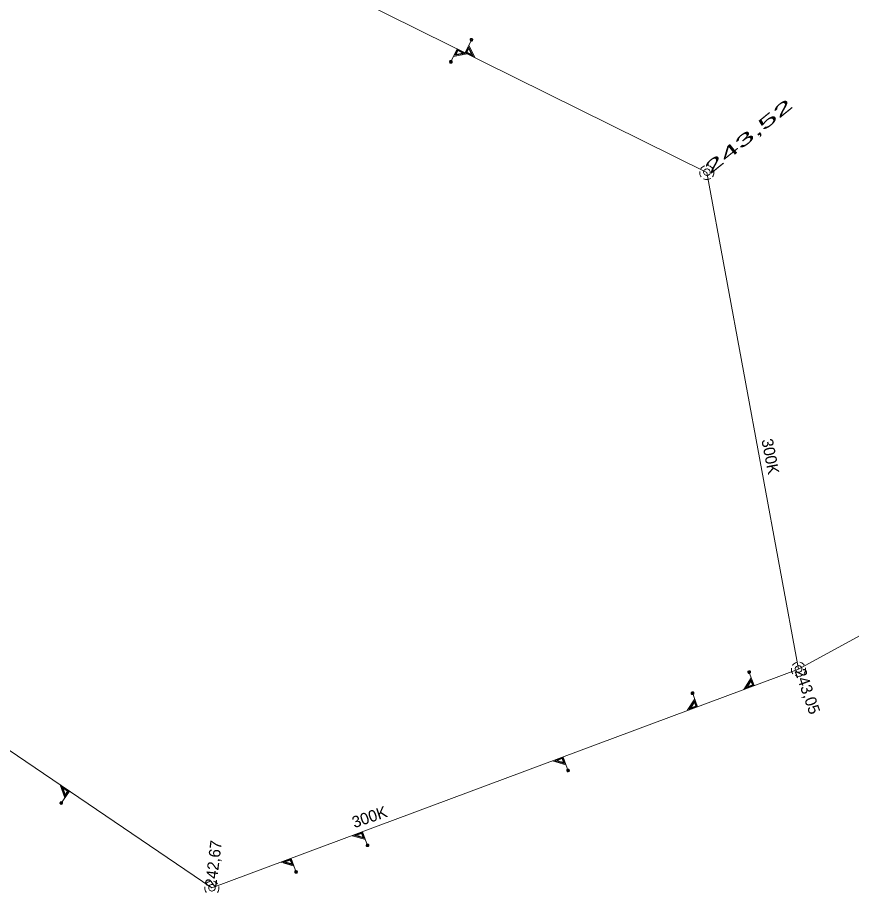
# Model space of a CAD drawing. Extents: x -735085 to -733500, y -1044153 to -1043402.
# Drawn here: x -734770.5 to -734712.5, y -1043657.9 to -1043597 of the extents above; entities that cross this region are included whole.
import ezdxf

# ---------------------------------------------------------------- set-up
doc = ezdxf.new("R2010")
doc.units = 0
doc.header["$LTSCALE"] = 0.32
doc.layers.add('16', color=7, linetype='Continuous')
doc.layers.add('18', color=7, linetype='Continuous', lineweight=13)
doc.layers.add('20', color=7, linetype='Continuous', lineweight=13)

msp = doc.modelspace()

# ---------------------------------------------------------------- linework, layer by layer
at = {"layer": '18'}
for points in [[(-734738.898, -1043598.489), (-734739.384, -1043599.471), (-734738.693, -1043599.812), (-734739.128, -1043598.953)], [(-734740.411, -1043600.192), (-734739.925, -1043599.21), (-734739.235, -1043599.551), (-734740.182, -1043599.728)], [(-734740.005, -1043599.59), (-734739.876, -1043599.328), (-734739.542, -1043599.493), (-734740.006, -1043599.59)], [(-734739.135, -1043599.082), (-734739.319, -1043599.455), (-734738.812, -1043599.706), (-734739.134, -1043599.08)], [(-734739.129, -1043599.177), (-734739.259, -1043599.439), (-734738.926, -1043599.603), (-734739.13, -1043599.177)], [(-734722.703, -1043607.337), (-734722.774, -1043607.365), (-734722.841, -1043607.404), (-734722.901, -1043607.452), (-734722.952, -1043607.509), (-734722.976, -1043607.543)], [(-734722.162, -1043607.52), (-734722.212, -1043607.462), (-734722.27, -1043607.412), (-734722.335, -1043607.371), (-734722.406, -1043607.342), (-734722.455, -1043607.328)], [(-734723.048, -1043607.729), (-734723.054, -1043607.806), (-734723.049, -1043607.883), (-734723.032, -1043607.958), (-734723.003, -1043608.029), (-734722.963, -1043608.095), (-734722.947, -1043608.117)], [(-734722.167, -1043608.106), (-734722.126, -1043608.041), (-734722.095, -1043607.971), (-734722.076, -1043607.896), (-734722.068, -1043607.82), (-734722.073, -1043607.743), (-734722.079, -1043607.708)], [(-734722.79, -1043608.246), (-734722.72, -1043608.277), (-734722.645, -1043608.296), (-734722.569, -1043608.303), (-734722.492, -1043608.298), (-734722.417, -1043608.281), (-734722.345, -1043608.253), (-734722.285, -1043608.218)], [(-734716.323, -1043641.907), (-734716.394, -1043641.935), (-734716.461, -1043641.974), (-734716.521, -1043642.022), (-734716.572, -1043642.079), (-734716.596, -1043642.113)], [(-734715.782, -1043642.09), (-734715.832, -1043642.032), (-734715.89, -1043641.982), (-734715.955, -1043641.941), (-734716.026, -1043641.912), (-734716.075, -1043641.898)], [(-734715.787, -1043642.676), (-734715.746, -1043642.611), (-734715.715, -1043642.541), (-734715.696, -1043642.466), (-734715.688, -1043642.39), (-734715.693, -1043642.313), (-734715.699, -1043642.278)], [(-734719.645, -1043642.492), (-734719.262, -1043643.518), (-734719.984, -1043643.787), (-734719.464, -1043642.976)], [(-734716.668, -1043642.299), (-734716.674, -1043642.376), (-734716.669, -1043642.453), (-734716.652, -1043642.528), (-734716.623, -1043642.599), (-734716.583, -1043642.665), (-734716.567, -1043642.687)], [(-734716.41, -1043642.816), (-734716.34, -1043642.847), (-734716.265, -1043642.866), (-734716.189, -1043642.873), (-734716.112, -1043642.868), (-734716.037, -1043642.851), (-734715.965, -1043642.823), (-734715.905, -1043642.788)], [(-734719.47, -1043643.104), (-734719.324, -1043643.494), (-734719.855, -1043643.692), (-734719.47, -1043643.103)], [(-734719.484, -1043643.2), (-734719.382, -1043643.473), (-734719.731, -1043643.603), (-734719.483, -1043643.199)], [(-734723.58, -1043643.96), (-734723.197, -1043644.986), (-734723.919, -1043645.255), (-734723.399, -1043644.444)], [(-734723.405, -1043644.572), (-734723.259, -1043644.962), (-734723.79, -1043645.16), (-734723.405, -1043644.571)], [(-734723.419, -1043644.668), (-734723.317, -1043644.941), (-734723.666, -1043645.071), (-734723.418, -1043644.667)], [(-734732.183, -1043649.513), (-734732.566, -1043648.487), (-734733.288, -1043648.757), (-734732.364, -1043649.029)], [(-734732.453, -1043648.935), (-734732.599, -1043648.545), (-734733.129, -1043648.743), (-734732.453, -1043648.937)], [(-734732.526, -1043648.874), (-734732.628, -1043648.6), (-734732.976, -1043648.73), (-734732.525, -1043648.873)], [(-734767.543, -1043651.765), (-734766.928, -1043650.859), (-734767.566, -1043650.426), (-734767.253, -1043651.337)], [(-734767.228, -1043651.21), (-734766.995, -1043650.866), (-734767.463, -1043650.548), (-734767.229, -1043651.212)], [(-734767.22, -1043651.115), (-734767.056, -1043650.874), (-734767.363, -1043650.665), (-734767.22, -1043651.116)], [(-734746.142, -1043654.72), (-734746.525, -1043653.694), (-734747.247, -1043653.964), (-734746.323, -1043654.236)], [(-734746.412, -1043654.142), (-734746.558, -1043653.752), (-734747.088, -1043653.95), (-734746.412, -1043654.144)], [(-734746.485, -1043654.081), (-734746.587, -1043653.807), (-734746.935, -1043653.937), (-734746.484, -1043654.08)], [(-734751.108, -1043656.572), (-734751.491, -1043655.546), (-734752.213, -1043655.816), (-734751.289, -1043656.088)], [(-734751.378, -1043655.994), (-734751.524, -1043655.604), (-734752.054, -1043655.802), (-734751.378, -1043655.996)], [(-734751.451, -1043655.933), (-734751.553, -1043655.659), (-734751.901, -1043655.789), (-734751.45, -1043655.932)], [(-734757.153, -1043657.137), (-734757.224, -1043657.165), (-734757.291, -1043657.204), (-734757.351, -1043657.252), (-734757.402, -1043657.309), (-734757.426, -1043657.343)], [(-734756.612, -1043657.32), (-734756.662, -1043657.262), (-734756.72, -1043657.212), (-734756.785, -1043657.171), (-734756.856, -1043657.142), (-734756.905, -1043657.128)], [(-734757.498, -1043657.529), (-734757.504, -1043657.606), (-734757.499, -1043657.683), (-734757.482, -1043657.758), (-734757.453, -1043657.829), (-734757.413, -1043657.895), (-734757.397, -1043657.917)], [(-734756.617, -1043657.906), (-734756.576, -1043657.841), (-734756.545, -1043657.771), (-734756.526, -1043657.696), (-734756.518, -1043657.62), (-734756.523, -1043657.543), (-734756.529, -1043657.508)]]:
    msp.add_lwpolyline(points, dxfattribs=at)
for points in [[(-734738.855, -1043598.615), (-734738.846, -1043598.583), (-734738.848, -1043598.55), (-734738.862, -1043598.519), (-734738.886, -1043598.496), (-734738.916, -1043598.482), (-734738.95, -1043598.48), (-734738.983, -1043598.49), (-734739.009, -1043598.51), (-734739.028, -1043598.538), (-734739.034, -1043598.572), (-734739.029, -1043598.604), (-734739.013, -1043598.633), (-734738.987, -1043598.655), (-734738.956, -1043598.667), (-734738.923, -1043598.667), (-734738.891, -1043598.655), (-734738.866, -1043598.633)], [(-734738.88, -1043598.605), (-734738.873, -1043598.578), (-734738.878, -1043598.549), (-734738.893, -1043598.526), (-734738.919, -1043598.512), (-734738.946, -1043598.508), (-734738.973, -1043598.516), (-734738.994, -1043598.534), (-734739.006, -1043598.561), (-734739.006, -1043598.589), (-734738.995, -1043598.614), (-734738.973, -1043598.634), (-734738.947, -1043598.642), (-734738.919, -1043598.639), (-734738.894, -1043598.624)], [(-734740.085, -1043599.645), (-734739.9, -1043599.272), (-734739.393, -1043599.523)], [(-734740.285, -1043600.149), (-734740.276, -1043600.117), (-734740.278, -1043600.083), (-734740.292, -1043600.053), (-734740.316, -1043600.03), (-734740.346, -1043600.016), (-734740.38, -1043600.014), (-734740.412, -1043600.023), (-734740.439, -1043600.044), (-734740.457, -1043600.072), (-734740.464, -1043600.104), (-734740.459, -1043600.138), (-734740.442, -1043600.167), (-734740.417, -1043600.188), (-734740.385, -1043600.201), (-734740.352, -1043600.201), (-734740.321, -1043600.188), (-734740.296, -1043600.166)], [(-734740.309, -1043600.136), (-734740.302, -1043600.108), (-734740.306, -1043600.081), (-734740.322, -1043600.058), (-734740.346, -1043600.043), (-734740.374, -1043600.039), (-734740.401, -1043600.048), (-734740.423, -1043600.066), (-734740.434, -1043600.092), (-734740.434, -1043600.12), (-734740.423, -1043600.146), (-734740.402, -1043600.165), (-734740.375, -1043600.174), (-734740.347, -1043600.17), (-734740.323, -1043600.156)], [(-734722.319, -1043607.789), (-734722.325, -1043607.737), (-734722.343, -1043607.687), (-734722.371, -1043607.643), (-734722.409, -1043607.606), (-734722.454, -1043607.579), (-734722.504, -1043607.563), (-734722.556, -1043607.558), (-734722.608, -1043607.565), (-734722.657, -1043607.584), (-734722.701, -1043607.614), (-734722.736, -1043607.653), (-734722.762, -1043607.698), (-734722.777, -1043607.749), (-734722.78, -1043607.801), (-734722.772, -1043607.853), (-734722.751, -1043607.901), (-734722.721, -1043607.944), (-734722.681, -1043607.979), (-734722.635, -1043608.003), (-734722.584, -1043608.017), (-734722.532, -1043608.019), (-734722.48, -1043608.009), (-734722.432, -1043607.987), (-734722.39, -1043607.955), (-734722.357, -1043607.915), (-734722.333, -1043607.868), (-734722.321, -1043607.817)], [(-734715.939, -1043642.359), (-734715.945, -1043642.307), (-734715.963, -1043642.257), (-734715.991, -1043642.213), (-734716.029, -1043642.176), (-734716.074, -1043642.149), (-734716.124, -1043642.133), (-734716.176, -1043642.128), (-734716.228, -1043642.135), (-734716.277, -1043642.154), (-734716.321, -1043642.184), (-734716.356, -1043642.223), (-734716.382, -1043642.268), (-734716.397, -1043642.319), (-734716.4, -1043642.371), (-734716.392, -1043642.423), (-734716.371, -1043642.471), (-734716.341, -1043642.514), (-734716.301, -1043642.549), (-734716.255, -1043642.573), (-734716.204, -1043642.587), (-734716.152, -1043642.589), (-734716.1, -1043642.579), (-734716.052, -1043642.557), (-734716.01, -1043642.525), (-734715.977, -1043642.485), (-734715.953, -1043642.438), (-734715.941, -1043642.387)], [(-734719.7, -1043642.613), (-734719.683, -1043642.642), (-734719.657, -1043642.663), (-734719.625, -1043642.674), (-734719.592, -1043642.672), (-734719.561, -1043642.659), (-734719.537, -1043642.636), (-734719.521, -1043642.606), (-734719.518, -1043642.573), (-734719.526, -1043642.541), (-734719.545, -1043642.513), (-734719.573, -1043642.494), (-734719.605, -1043642.486), (-734719.638, -1043642.49), (-734719.669, -1043642.504), (-734719.692, -1043642.529), (-734719.704, -1043642.56), (-734719.705, -1043642.593)], [(-734719.674, -1043642.604), (-734719.659, -1043642.629), (-734719.636, -1043642.645), (-734719.608, -1043642.648), (-734719.581, -1043642.641), (-734719.559, -1043642.623), (-734719.547, -1043642.597), (-734719.546, -1043642.569), (-734719.556, -1043642.543), (-734719.576, -1043642.524), (-734719.603, -1043642.515), (-734719.631, -1043642.517), (-734719.656, -1043642.53), (-734719.673, -1043642.554), (-734719.679, -1043642.581)], [(-734723.635, -1043644.081), (-734723.618, -1043644.11), (-734723.592, -1043644.131), (-734723.56, -1043644.142), (-734723.527, -1043644.14), (-734723.496, -1043644.127), (-734723.472, -1043644.104), (-734723.456, -1043644.074), (-734723.453, -1043644.041), (-734723.461, -1043644.009), (-734723.48, -1043643.981), (-734723.508, -1043643.962), (-734723.54, -1043643.954), (-734723.573, -1043643.958), (-734723.604, -1043643.972), (-734723.627, -1043643.997), (-734723.639, -1043644.028), (-734723.64, -1043644.061)], [(-734723.609, -1043644.072), (-734723.594, -1043644.097), (-734723.571, -1043644.113), (-734723.543, -1043644.116), (-734723.516, -1043644.109), (-734723.494, -1043644.091), (-734723.482, -1043644.065), (-734723.481, -1043644.037), (-734723.491, -1043644.011), (-734723.511, -1043643.992), (-734723.538, -1043643.983), (-734723.566, -1043643.985), (-734723.591, -1043643.998), (-734723.608, -1043644.022), (-734723.614, -1043644.049)], [(-734732.305, -1043649.458), (-734732.288, -1043649.487), (-734732.262, -1043649.508), (-734732.23, -1043649.519), (-734732.197, -1043649.517), (-734732.166, -1043649.505), (-734732.142, -1043649.482), (-734732.126, -1043649.451), (-734732.123, -1043649.418), (-734732.13, -1043649.386), (-734732.15, -1043649.358), (-734732.178, -1043649.339), (-734732.21, -1043649.331), (-734732.243, -1043649.335), (-734732.273, -1043649.349), (-734732.296, -1043649.374), (-734732.309, -1043649.405), (-734732.31, -1043649.439)], [(-734732.28, -1043649.447), (-734732.265, -1043649.471), (-734732.241, -1043649.487), (-734732.214, -1043649.491), (-734732.186, -1043649.483), (-734732.165, -1043649.466), (-734732.152, -1043649.441), (-734732.15, -1043649.412), (-734732.161, -1043649.386), (-734732.182, -1043649.367), (-734732.208, -1043649.357), (-734732.237, -1043649.359), (-734732.261, -1043649.373), (-734732.278, -1043649.396), (-734732.285, -1043649.424)], [(-734767.569, -1043651.634), (-734767.583, -1043651.665), (-734767.585, -1043651.698), (-734767.575, -1043651.73), (-734767.554, -1043651.756), (-734767.526, -1043651.774), (-734767.493, -1043651.781), (-734767.46, -1043651.776), (-734767.431, -1043651.759), (-734767.409, -1043651.734), (-734767.398, -1043651.702), (-734767.398, -1043651.669), (-734767.41, -1043651.638), (-734767.433, -1043651.613), (-734767.462, -1043651.597), (-734767.495, -1043651.592), (-734767.528, -1043651.6), (-734767.556, -1043651.619)], [(-734767.546, -1043651.648), (-734767.556, -1043651.674), (-734767.555, -1043651.703), (-734767.543, -1043651.728), (-734767.52, -1043651.746), (-734767.494, -1043651.753), (-734767.466, -1043651.749), (-734767.442, -1043651.734), (-734767.427, -1043651.709), (-734767.423, -1043651.681), (-734767.431, -1043651.654), (-734767.449, -1043651.632), (-734767.474, -1043651.62), (-734767.503, -1043651.62), (-734767.529, -1043651.631)], [(-734746.264, -1043654.665), (-734746.247, -1043654.694), (-734746.221, -1043654.715), (-734746.189, -1043654.726), (-734746.156, -1043654.724), (-734746.125, -1043654.712), (-734746.101, -1043654.689), (-734746.085, -1043654.658), (-734746.082, -1043654.625), (-734746.089, -1043654.593), (-734746.109, -1043654.565), (-734746.137, -1043654.546), (-734746.169, -1043654.538), (-734746.202, -1043654.542), (-734746.232, -1043654.556), (-734746.255, -1043654.581), (-734746.268, -1043654.612), (-734746.269, -1043654.646)], [(-734746.239, -1043654.654), (-734746.224, -1043654.678), (-734746.2, -1043654.694), (-734746.173, -1043654.698), (-734746.145, -1043654.69), (-734746.124, -1043654.673), (-734746.111, -1043654.648), (-734746.109, -1043654.619), (-734746.12, -1043654.593), (-734746.141, -1043654.574), (-734746.167, -1043654.564), (-734746.196, -1043654.566), (-734746.22, -1043654.58), (-734746.237, -1043654.603), (-734746.244, -1043654.631)], [(-734751.23, -1043656.517), (-734751.213, -1043656.546), (-734751.187, -1043656.567), (-734751.155, -1043656.578), (-734751.122, -1043656.576), (-734751.091, -1043656.564), (-734751.067, -1043656.541), (-734751.051, -1043656.51), (-734751.048, -1043656.477), (-734751.055, -1043656.445), (-734751.075, -1043656.417), (-734751.103, -1043656.398), (-734751.135, -1043656.39), (-734751.168, -1043656.394), (-734751.198, -1043656.408), (-734751.221, -1043656.433), (-734751.234, -1043656.464), (-734751.235, -1043656.498)], [(-734751.205, -1043656.506), (-734751.19, -1043656.53), (-734751.166, -1043656.546), (-734751.139, -1043656.55), (-734751.111, -1043656.542), (-734751.09, -1043656.525), (-734751.077, -1043656.5), (-734751.075, -1043656.471), (-734751.086, -1043656.445), (-734751.107, -1043656.426), (-734751.133, -1043656.416), (-734751.162, -1043656.418), (-734751.186, -1043656.432), (-734751.203, -1043656.455), (-734751.21, -1043656.483)], [(-734756.769, -1043657.589), (-734756.775, -1043657.537), (-734756.793, -1043657.487), (-734756.821, -1043657.443), (-734756.859, -1043657.406), (-734756.904, -1043657.379), (-734756.954, -1043657.363), (-734757.006, -1043657.358), (-734757.058, -1043657.365), (-734757.107, -1043657.384), (-734757.151, -1043657.414), (-734757.186, -1043657.453), (-734757.212, -1043657.498), (-734757.227, -1043657.549), (-734757.23, -1043657.601), (-734757.222, -1043657.653), (-734757.201, -1043657.701), (-734757.171, -1043657.744), (-734757.131, -1043657.779), (-734757.085, -1043657.803), (-734757.034, -1043657.817), (-734756.982, -1043657.819), (-734756.93, -1043657.809), (-734756.882, -1043657.787), (-734756.84, -1043657.755), (-734756.807, -1043657.715), (-734756.783, -1043657.668), (-734756.771, -1043657.617)]]:
    msp.add_lwpolyline(points, close=True, dxfattribs=at)
at = {"layer": '20'}
for p, q in [((-734767.879, -1043585.38), (-734722.55, -1043607.8)), ((-734767.879, -1043585.38), (-734722.55, -1043607.8)), ((-734722.55, -1043607.8), (-734716.17, -1043642.37)), ((-734722.55, -1043607.8), (-734716.17, -1043642.37)), ((-734684.89, -1043625.26), (-734716.17, -1043642.37)), ((-734684.89, -1043625.26), (-734716.17, -1043642.37))]:
    msp.add_line(p, q, dxfattribs=at)
msp.add_lwpolyline([(-734716.17, -1043642.37), (-734757, -1043657.6), (-734791.539, -1043634.15)], dxfattribs=at)
msp.add_lwpolyline([(-734716.17, -1043642.37), (-734757, -1043657.6), (-734791.539, -1043634.15)], dxfattribs=at)

# ---------------------------------------------------------------- texts
at = {"layer": '16', "width": 2.3}
msp.add_text('243,52', height=0.8, rotation=39, dxfattribs=at).set_placement((-734722.332, -1043607.967))
at = {"layer": '16'}
for s, rotation, p in [('300K', 281, (-734718.762, -1043626.419)), ('243,05', 289, (-734716.46, -1043642.498)), ('300K', 19, (-734747.088, -1043653.443)), ('242,67', 83, (-734756.705, -1043657.593))]:
    msp.add_text(s, height=0.8, rotation=rotation, dxfattribs=at).set_placement(p)

doc.saveas('drawing.dxf')
